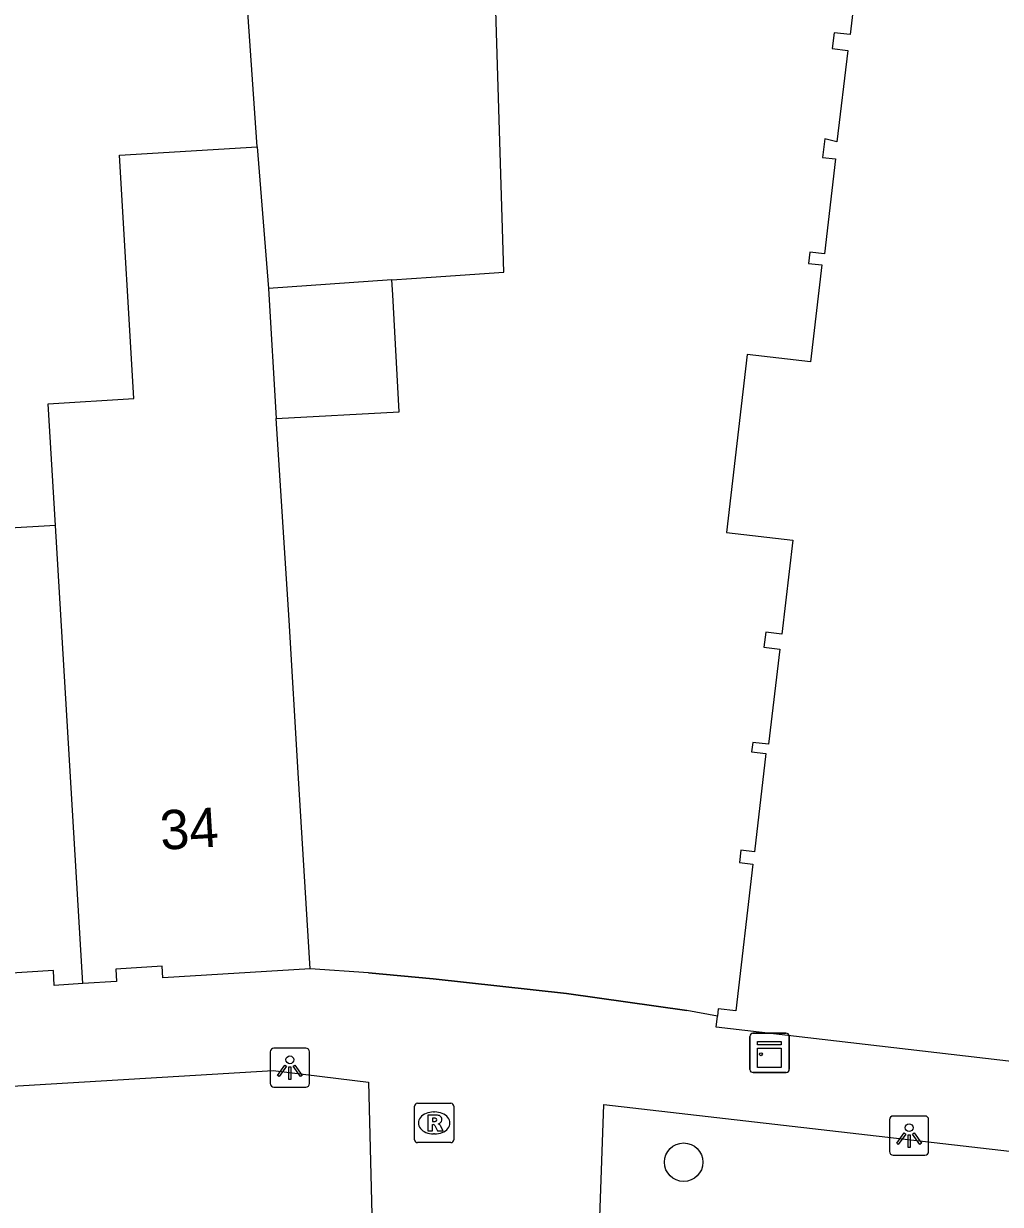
# Model space of a CAD drawing. Extents: x 160861 to 161308, y 384024 to 384878.
# Drawn here: x 161178.37 to 161203.22, y 384304.92 to 384334.96 of the extents above; entities that cross this region are included whole.
import ezdxf

# ---------------------------------------------------------------- set-up
doc = ezdxf.new("R2010")
doc.units = 0
for name, color, linetype in [('IMGEO_Boom', 7, 'Continuous'), ('IMGEO_Hek', 7, 'Continuous'), ('IMGEO_Kast', 7, 'Continuous'), ('IMGEO_Lichtpunt', 7, 'Continuous'), ('IMGEO_Muur', 7, 'Continuous'), ('IMGEO_Pand', 7, 'Continuous'), ('IMGEO_Pand_nummerreeks', 7, 'Continuous'), ('IMGEO_Rioolput', 7, 'Continuous'), ('IMGEO_Voetpad_open', 7, 'Continuous')]:
    doc.layers.add(name, color=color, linetype=linetype)

msp = doc.modelspace()

# ---------------------------------------------------------------- linework, layer by layer
at = {"layer": 'IMGEO_Boom'}
msp.add_circle((161195.165, 384305.993), 0.489, dxfattribs=at)
at = {"layer": 'IMGEO_Hek'}
msp.add_lwpolyline([(161188.793, 384310.655), (161192.181, 384310.284)], dxfattribs=at)
at = {"layer": 'IMGEO_Kast'}
for p, q in [((161196.852, 384308.351), (161196.852, 384309.192)), ((161196.852, 384309.192), (161196.852, 384308.351)), ((161196.927, 384309.276), (161197.768, 384309.276)), ((161197.768, 384309.276), (161196.927, 384309.276)), ((161197.852, 384309.201), (161197.852, 384308.36)), ((161197.852, 384308.36), (161197.852, 384309.201)), ((161197.777, 384308.276), (161196.936, 384308.276)), ((161196.936, 384308.276), (161197.777, 384308.276))]:
    msp.add_line(p, q, dxfattribs=at)
for points in [[(161197.047, 384309.066), (161197.647, 384309.066), (161197.647, 384308.981), (161197.047, 384308.981), (161197.047, 384309.066)], [(161197.047, 384308.891), (161197.647, 384308.891), (161197.647, 384308.402), (161197.047, 384308.402), (161197.047, 384308.891)]]:
    msp.add_lwpolyline(points, dxfattribs=at)
msp.add_circle((161197.131, 384308.74), 0.0377, dxfattribs=at)
for centre, start, end in [((161196.93, 384309.198), 92.4484, 184.2845), ((161196.93, 384309.198), 92.4484, 184.2845), ((161197.774, 384309.198), 2.4484, 94.2845), ((161197.774, 384309.198), 2.4484, 94.2845), ((161196.93, 384308.354), 182.4484, 274.2845), ((161196.93, 384308.354), 182.4484, 274.2845), ((161197.774, 384308.354), 272.4484, 4.2845), ((161197.774, 384308.354), 272.4484, 4.2845)]:
    msp.add_arc(centre, 0.0779, start, end, dxfattribs=at)
at = {"layer": 'IMGEO_Lichtpunt'}
for p, q in [((161185.55, 384308.896), (161184.742, 384308.896)), ((161185.55, 384308.896), (161184.742, 384308.896)), ((161184.648, 384308.801), (161184.648, 384307.994)), ((161184.648, 384308.801), (161184.648, 384307.994)), ((161185.644, 384307.994), (161185.644, 384308.801)), ((161185.644, 384307.994), (161185.644, 384308.801)), ((161184.742, 384307.9), (161185.55, 384307.9)), ((161184.742, 384307.9), (161185.55, 384307.9)), ((161201.304, 384307.168), (161200.496, 384307.168)), ((161201.304, 384307.168), (161200.496, 384307.168)), ((161200.402, 384307.073), (161200.402, 384306.266)), ((161200.402, 384307.073), (161200.402, 384306.266)), ((161201.398, 384306.266), (161201.398, 384307.073)), ((161201.398, 384306.266), (161201.398, 384307.073)), ((161200.496, 384306.172), (161201.304, 384306.172)), ((161200.496, 384306.172), (161201.304, 384306.172))]:
    msp.add_line(p, q, dxfattribs=at)
for points in [[(161185.022, 384308.465), (161185.061, 384308.437), (161184.873, 384308.175), (161184.835, 384308.202), (161185.022, 384308.465)], [(161185.124, 384308.417), (161185.171, 384308.417), (161185.171, 384308.095), (161185.124, 384308.095), (161185.124, 384308.417)], [(161185.234, 384308.437), (161185.272, 384308.464), (161185.459, 384308.202), (161185.42, 384308.174), (161185.234, 384308.437)], [(161200.776, 384306.737), (161200.815, 384306.709), (161200.627, 384306.447), (161200.589, 384306.474), (161200.776, 384306.737)], [(161200.878, 384306.689), (161200.925, 384306.689), (161200.925, 384306.367), (161200.878, 384306.367), (161200.878, 384306.689)], [(161200.988, 384306.709), (161201.026, 384306.736), (161201.213, 384306.474), (161201.174, 384306.446), (161200.988, 384306.709)]]:
    msp.add_lwpolyline(points, dxfattribs=at)
for centre in [(161185.147, 384308.599), (161200.901, 384306.871)]:
    msp.add_circle(centre, 0.0994, dxfattribs=at)
for centre, start, end in [((161184.742, 384308.801), 90, 180), ((161184.742, 384308.801), 90, 180), ((161185.55, 384308.801), 0, 90), ((161185.55, 384308.801), 0, 90), ((161184.742, 384307.994), 180, 270), ((161184.742, 384307.994), 180, 270), ((161185.55, 384307.994), 270, 0), ((161185.55, 384307.994), 270, 360), ((161200.496, 384307.073), 90, 180), ((161200.496, 384307.073), 90, 180), ((161201.304, 384307.073), 0, 90), ((161201.304, 384307.073), 0, 90), ((161200.496, 384306.266), 180, 270), ((161200.496, 384306.266), 180, 270), ((161201.304, 384306.266), 270, 0), ((161201.304, 384306.266), 270, 360)]:
    msp.add_arc(centre, 0.0946, start, end, dxfattribs=at)
at = {"layer": 'IMGEO_Muur'}
for points in [[(161187.145, 384310.814), (161188.793, 384310.655)], [(161192.181, 384310.284), (161195.244, 384309.849)]]:
    msp.add_lwpolyline(points, dxfattribs=at)
at = {"layer": 'IMGEO_Pand'}
for points in [[(161187.744, 384328.443), (161188.742, 384328.511), (161190.59, 384328.638), (161189.735, 384356.643), (161184.071, 384356.465)], [(161184.31, 384331.83), (161183.32, 384346.153)], [(161199.851, 384338.533), (161199.404, 384334.684), (161198.994, 384334.732), (161198.947, 384334.328), (161199.34, 384334.283), (161199.062, 384331.956), (161198.755, 384332.03), (161198.7, 384331.562), (161199.032, 384331.524), (161198.751, 384329.103), (161198.376, 384329.147), (161198.343, 384328.863), (161198.678, 384328.824), (161198.392, 384326.36), (161196.778, 384326.548), (161196.252, 384322.016), (161197.944, 384321.82), (161197.666, 384319.429), (161197.252, 384319.477), (161197.207, 384319.094), (161197.608, 384319.047), (161197.326, 384316.628), (161196.923, 384316.674), (161196.895, 384316.434), (161197.257, 384316.392), (161196.966, 384313.891), (161196.623, 384313.931), (161196.586, 384313.616), (161196.924, 384313.577), (161196.49, 384309.843), (161196.047, 384309.894), (161196.025, 384309.707)], [(161179.181, 384322.198), (161178.996, 384325.294), (161181.179, 384325.426), (161180.808, 384331.62), (161184.31, 384331.83)], [(161184.31, 384331.83), (161184.604, 384328.227)], [(161187.744, 384328.443), (161184.604, 384328.227)], [(161184.799, 384324.913), (161187.926, 384325.082), (161187.765, 384328.062), (161187.744, 384328.443)], [(161184.604, 384328.227), (161184.799, 384324.913)], [(161185.661, 384310.911), (161185.36, 384315.902), (161185.126, 384319.785), (161184.799, 384324.913)], [(161179.181, 384322.198), (161176.421, 384322.032), (161176.586, 384319.304), (161173.854, 384319.139)], [(161179.879, 384310.537), (161179.181, 384322.198)], [(161179.879, 384310.537), (161179.152, 384310.493), (161179.129, 384310.87), (161177.932, 384310.798), (161177.955, 384310.422), (161174.39, 384310.207)], [(161185.661, 384310.911), (161181.914, 384310.686), (161181.897, 384310.979), (161180.718, 384310.908), (161180.737, 384310.588), (161179.879, 384310.537)], [(161209.191, 384307.893), (161195.993, 384309.427), (161196.025, 384309.707)]]:
    msp.add_lwpolyline(points, dxfattribs=at)
at = {"layer": 'IMGEO_Rioolput'}
for p, q in [((161188.316, 384306.565), (161188.316, 384307.417)), ((161188.391, 384307.491), (161189.243, 384307.491)), ((161189.317, 384307.417), (161189.317, 384306.565)), ((161188.804, 384307.271), (161188.829, 384307.271)), ((161189.243, 384306.491), (161188.391, 384306.491)), ((161188.827, 384306.711), (161188.802, 384306.711))]:
    msp.add_line(p, q, dxfattribs=at)
for points in [[(161188.316, 384306.565), (161188.316, 384307.417)], [(161188.391, 384307.491), (161189.243, 384307.491)], [(161189.317, 384307.417), (161189.317, 384306.565)], [(161188.905, 384307.189), (161188.653, 384307.191), (161188.653, 384306.791)], [(161188.831, 384307.11), (161188.777, 384307.11), (161188.777, 384307.029)], [(161188.653, 384306.791), (161188.777, 384306.791), (161188.777, 384306.953), (161188.788, 384306.953)], [(161188.777, 384307.029), (161188.829, 384307.029)], [(161188.835, 384306.924), (161188.906, 384306.791), (161189.046, 384306.791), (161188.981, 384306.917)], [(161189.243, 384306.491), (161188.391, 384306.491)]]:
    msp.add_lwpolyline(points, dxfattribs=at)
for centre, radius, start, end in [((161188.393, 384307.415), 0.0765, 91.552, 178.448), ((161188.393, 384307.415), 0.0765, 91.552, 178.448), ((161189.241, 384307.415), 0.0765, 1.552, 88.448), ((161189.241, 384307.415), 0.0765, 1.552, 88.448), ((161188.837, 384307.014), 0.0964, 77.0061, 93.1865), ((161188.851, 384307.071), 0.0378, 276.6634, 79.6772), ((161188.904, 384307.079), 0.109, 350.3612, 89.416), ((161188.787, 384306.9), 0.0533, 26.0293, 88.6989), ((161188.813, 384307.218), 0.19, 274.7715, 282.9687), ((161188.902, 384307.079), 0.112, 277.5842, 350.9817), ((161188.886, 384306.864), 0.108, 29.5134, 73.7905), ((161188.393, 384306.567), 0.0765, 181.552, 268.448), ((161188.393, 384306.567), 0.0765, 181.552, 268.448), ((161189.241, 384306.567), 0.0765, 271.552, 358.448), ((161189.241, 384306.567), 0.0765, 271.552, 358.448)]:
    msp.add_arc(centre, radius, start, end, dxfattribs=at)
for centre, major_axis, ratio, start_param, end_param in [((161188.803, 384306.991), (-0.387, 0.002), 0.722429, 4.712389, 7.853982), ((161188.828, 384306.991), (-0.39, 0.002), 0.717154, 1.570796, 4.712389)]:
    msp.add_ellipse(centre, major_axis=major_axis, ratio=ratio, start_param=start_param, end_param=end_param, dxfattribs=at)
at = {"layer": 'IMGEO_Voetpad_open'}
for points in [[(161196.025, 384309.707), (161195.244, 384309.849), (161192.181, 384310.284), (161188.793, 384310.655), (161187.145, 384310.814), (161185.661, 384310.911)], [(161172.837, 384304.619), (161172.712, 384307.603), (161184.724, 384308.326), (161187.148, 384308.033), (161187.229, 384304.664)], [(161193.029, 384304.59), (161193.135, 384307.46), (161208.985, 384305.639), (161208.876, 384304.774), (161207.771, 384304.807), (161207.639, 384302.974), (161208.64, 384302.912), (161208.399, 384301.003), (161205.958, 384300.995)]]:
    msp.add_lwpolyline(points, dxfattribs=at)

# ---------------------------------------------------------------- texts
at = {"layer": 'IMGEO_Pand_nummerreeks'}
msp.add_text('34', height=1, rotation=3.4452, dxfattribs=at).set_placement((161181.871, 384313.938))

doc.saveas('drawing.dxf')
